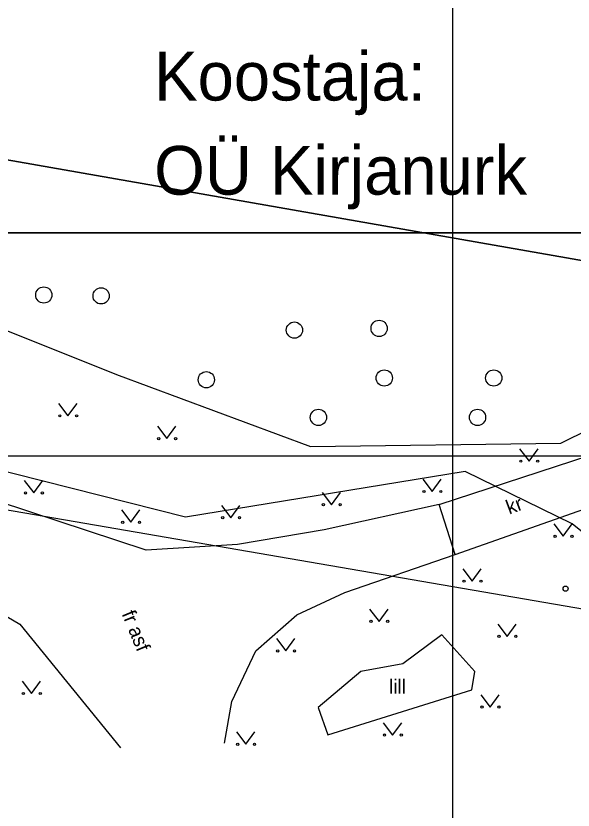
# Model space of a CAD drawing. Extents: x 554947 to 555436, y 6564938 to 6565792.
# Drawn here: x 555195.59 to 555223.03, y 6565130.48 to 6565169.6 of the extents above; entities that cross this region are included whole.
import ezdxf

# ---------------------------------------------------------------- set-up
doc = ezdxf.new("R2010")
doc.units = 0
for name, color, linetype in [('HALJASTUS', 7, 'Continuous'), ('KPOHULIIN', 7, 'Continuous'), ('PIIR', 7, 'Continuous'), ('PR_SIDE', 7, 'Continuous'), ('PUU', 7, 'Continuous'), ('TEE', 7, 'Continuous'), ('VORMISTUS', 7, 'Continuous'), ('VORMISTUS_1', 7, 'Continuous')]:
    doc.layers.add(name, color=color, linetype=linetype)

msp = doc.modelspace()

# ---------------------------------------------------------------- linework, layer by layer
at = {"layer": 'HALJASTUS'}
for p, q in [((555197.689, 6565150.508), (555198.153, 6565149.901)), ((555198.153, 6565149.901), (555198.598, 6565150.508)), ((555202.562, 6565149.385), (555203.025, 6565148.778)), ((555203.025, 6565148.778), (555203.471, 6565149.385)), ((555220.397, 6565148.274), (555220.861, 6565147.667)), ((555220.861, 6565147.667), (555221.306, 6565148.274)), ((555196, 6565146.709), (555196.464, 6565146.102)), ((555196.464, 6565146.102), (555196.909, 6565146.709)), ((555215.626, 6565146.78), (555216.089, 6565146.173)), ((555216.089, 6565146.173), (555216.535, 6565146.78)), ((555210.669, 6565146.129), (555211.133, 6565145.522)), ((555211.133, 6565145.522), (555211.578, 6565146.129)), ((555205.711, 6565145.488), (555206.174, 6565144.881)), ((555206.174, 6565144.881), (555206.62, 6565145.488)), ((555200.786, 6565145.261), (555201.25, 6565144.654)), ((555201.25, 6565144.654), (555201.695, 6565145.261)), ((555222.085, 6565144.574), (555222.548, 6565143.967)), ((555222.548, 6565143.967), (555222.994, 6565144.574)), ((555217.602, 6565142.361), (555218.065, 6565141.754)), ((555218.065, 6565141.754), (555218.511, 6565142.361)), ((555213.012, 6565140.378), (555213.475, 6565139.771)), ((555213.475, 6565139.771), (555213.921, 6565140.378)), ((555219.32, 6565139.641), (555219.783, 6565139.034)), ((555219.783, 6565139.034), (555220.229, 6565139.641)), ((555208.419, 6565138.924), (555208.883, 6565138.317)), ((555208.883, 6565138.317), (555209.328, 6565138.924)), ((555195.895, 6565136.829), (555196.358, 6565136.222)), ((555196.358, 6565136.222), (555196.804, 6565136.829)), ((555218.486, 6565136.16), (555218.949, 6565135.553)), ((555218.949, 6565135.553), (555219.395, 6565136.16)), ((555213.68, 6565134.781), (555214.143, 6565134.175)), ((555214.143, 6565134.175), (555214.589, 6565134.781)), ((555206.451, 6565134.328), (555206.914, 6565133.721)), ((555206.914, 6565133.721), (555207.36, 6565134.328))]:
    msp.add_line(p, q, dxfattribs=at)
for points in [[(555170.849, 6565163.433), (555170.802, 6565162.422), (555180.588, 6565157.338), (555194.166, 6565154.476), (555200.547, 6565151.934), (555210.105, 6565148.383), (555222.421, 6565148.556), (555228.239, 6565151.421), (555231.104, 6565153.786)], [(555216.57, 6565139.116), (555214.639, 6565137.676), (555212.583, 6565137.299), (555210.474, 6565135.526), (555210.946, 6565134.177), (555218.038, 6565136.397), (555218.195, 6565137.306), (555216.57, 6565139.116)]]:
    msp.add_lwpolyline(points, dxfattribs=at)
for centre, radius in [((555196.963, 6565155.852), 0.4), ((555199.786, 6565155.81), 0.4), ((555209.308, 6565154.124), 0.4), ((555213.479, 6565154.208), 0.4), ((555213.732, 6565151.763), 0.4), ((555219.125, 6565151.763), 0.4), ((555204.968, 6565151.678), 0.4), ((555210.488, 6565149.823), 0.4), ((555218.325, 6565149.823), 0.4), ((555197.752, 6565149.901), 0.055), ((555198.581, 6565149.901), 0.055), ((555202.624, 6565148.778), 0.055), ((555203.453, 6565148.778), 0.055), ((555220.46, 6565147.667), 0.055), ((555221.289, 6565147.667), 0.055), ((555215.688, 6565146.173), 0.055), ((555216.517, 6565146.173), 0.055), ((555196.063, 6565146.102), 0.055), ((555196.892, 6565146.102), 0.055), ((555210.732, 6565145.522), 0.055), ((555211.56, 6565145.522), 0.055), ((555200.848, 6565144.654), 0.055), ((555201.677, 6565144.654), 0.055), ((555205.773, 6565144.881), 0.055), ((555206.602, 6565144.881), 0.055), ((555222.147, 6565143.967), 0.055), ((555222.976, 6565143.967), 0.055), ((555217.664, 6565141.754), 0.055), ((555218.493, 6565141.754), 0.055), ((555213.074, 6565139.771), 0.055), ((555213.903, 6565139.771), 0.055), ((555219.382, 6565139.034), 0.055), ((555220.211, 6565139.034), 0.055), ((555208.482, 6565138.317), 0.055), ((555209.311, 6565138.317), 0.055), ((555195.957, 6565136.222), 0.055), ((555196.786, 6565136.222), 0.055), ((555218.548, 6565135.553), 0.055), ((555219.377, 6565135.553), 0.055), ((555213.742, 6565134.175), 0.055), ((555214.571, 6565134.175), 0.055), ((555206.513, 6565133.721), 0.055), ((555207.342, 6565133.721), 0.055)]:
    msp.add_circle(centre, radius, dxfattribs=at)
at = {"layer": 'KPOHULIIN'}
msp.add_lwpolyline([(555148.701, 6565153.258), (555226.644, 6565139.855), (555319.309, 6565121.586)], dxfattribs=at)
at = {"layer": 'PIIR'}
for points in [[(555293.54, 6565286.23), (555256.63, 6565245.54), (555254.61, 6565228.5), (555255.75, 6565226.79), (555261.42, 6565218.27), (555289.11, 6565186.6), (555315.28, 6565149.09), (555315.73, 6565134.86), (555310.07, 6565124.47), (555303.59, 6565115.89), (555291.54, 6565100.48), (555288.85, 6565092.31), (555275.41, 6565088.83), (555273.15, 6565087.34), (555239.11, 6565139), (555231.12, 6565150.64), (555225.89, 6565157.13), (555173.21, 6565166.35), (555173.84, 6565168.77), (555191.64, 6565237.48), (555195.28, 6565271.63)], [(555272.013, 6565013.369), (555140.74, 6565041.04), (555172.58, 6565163.93), (555173.21, 6565166.35), (555225.89, 6565157.13), (555231.12, 6565150.64), (555239.11, 6565139), (555273.15, 6565087.34), (555275.41, 6565088.83), (555288.85, 6565092.31), (555289.83, 6565088.53), (555290.166, 6565088.221)]]:
    msp.add_lwpolyline(points, dxfattribs=at)
at = {"layer": 'PR_SIDE'}
msp.add_lwpolyline([(555239.586, 6565136.265), (555231.314, 6565137.915), (555222.994, 6565144.574), (555217.72, 6565147.16), (555203.944, 6565144.9), (555175.818, 6565152.015), (555174.729, 6565152.29), (555157.882, 6565156.552), (555156.917, 6565156.236), (555156.491, 6565155.453), (555155.859, 6565155.17)], dxfattribs=at)
at = {"layer": 'PUU'}
msp.add_circle((555222.663, 6565141.385), 0.125, dxfattribs=at)
at = {"layer": 'TEE'}
for points in [[(555205.86, 6565133.779), (555206.217, 6565135.824), (555207.407, 6565138.329), (555209.429, 6565140.104), (555211.794, 6565141.192), (555217.229, 6565143.067), (555216.442, 6565145.526), (555210.771, 6565144.283), (555206.511, 6565143.557), (555202.006, 6565143.277), (555191.831, 6565146.626), (555179.65, 6565150.043), (555174.155, 6565151.803), (555172.54, 6565153.141), (555170.207, 6565157.377), (555168.463, 6565160.669), (555168.3, 6565162.209)], [(555216.442, 6565145.526), (555223.819, 6565147.942), (555228.422, 6565150.319), (555233.413, 6565153.879)], [(555217.229, 6565143.067), (555224.725, 6565145.706), (555229.126, 6565147.942), (555234.467, 6565152.147)], [(555163.2, 6565141.618), (555168.594, 6565144.246), (555172.571, 6565146.598), (555178.227, 6565145.611), (555191.847, 6565141.953), (555195.778, 6565139.63), (555200.739, 6565133.541)]]:
    msp.add_lwpolyline(points, dxfattribs=at)
at = {"layer": 'VORMISTUS'}
msp.add_lwpolyline([(555217.086, 6564974.913), (555052.086, 6564974.913), (555052.086, 6565184.913), (555217.086, 6565184.913)], close=True, dxfattribs=at)
at = {"layer": 'VORMISTUS_1'}
for points in [[(555035.188, 6565444.913), (555245.188, 6565444.913), (555245.188, 6565147.913), (555035.188, 6565147.913)], [(555045.188, 6565158.913), (555235.188, 6565158.913), (555235.188, 6565433.913), (555045.188, 6565433.913)], [(555045.188, 6565433.913), (555235.188, 6565433.913), (555235.188, 6565158.913), (555045.188, 6565158.913)]]:
    msp.add_lwpolyline(points, close=True, dxfattribs=at)

# ---------------------------------------------------------------- texts
at = {"layer": 'HALJASTUS'}
msp.add_text('lill', height=0.7, dxfattribs=at).set_placement((555213.967, 6565136.212))
at = {"layer": 'TEE'}
for s, rotation, p in [('kr', 20.4711, (555219.887, 6565145.031)), ('fr asf', 292.2646, (555200.789, 6565140.147))]:
    msp.add_text(s, height=0.7, rotation=rotation, dxfattribs=at).set_placement(p)
at = {"layer": 'VORMISTUS_1'}
for s, p in [('Koostaja:', (555202.397, 6565165.434)), ('OÜ Kirjanurk', (555202.397, 6565160.796))]:
    msp.add_text(s, height=2.4, rotation=360, dxfattribs=at).set_placement(p)

doc.saveas('drawing.dxf')
